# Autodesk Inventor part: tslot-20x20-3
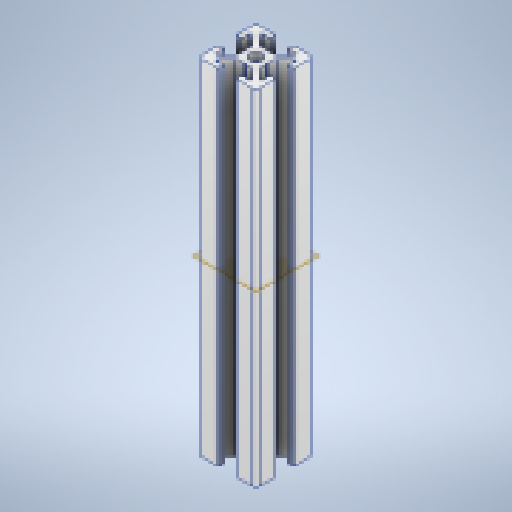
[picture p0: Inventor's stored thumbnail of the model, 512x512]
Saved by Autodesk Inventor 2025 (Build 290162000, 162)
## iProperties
Created: 2025-03
Part Number: tslot-20x20-3
Material: Alluminio 6061
Document SubType Name: Modeling
Designer: Ryzen5700u
Density: 2.7 g/cm^3
Appearance: Alluminio - Piatto
Author: Ryzen5700u
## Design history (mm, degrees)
feature "Base1"
sketch "Schizzo1"
  geometry: L1 (3.761, -16)-(4.7, -16) reference; L2 (3.761, -16)-(0.7, -12.939) reference; L3 (0.7, -12.939)-(0.7, -10.52) reference; L4 (0.4, -10)-(0.7, -10.52) reference; L5 (0.4, -10)-(0.7, -9.48) reference; L6 (0.7, -7.061)-(0.7, -9.48) reference; L7 (3.761, -4)-(0.7, -7.061) reference; L8 (3.761, -4)-(4.7, -4) reference; L9 (4.7, -4)-(4.7, -7) reference; L10 (4.7, -7)-(6.4, -7) reference; L11 (6.7, -6.7)-(6.7, -1) reference; L12 (5.7, 0)-(0, 0) reference; L13 (-0.3, -2)-(-0.3, -0.3) reference; L14 (2.7, -2)-(-0.3, -2) reference; L15 (2.7, -2.939)-(2.7, -2) reference; L16 (2.7, -2.939)-(-0.361, -6) reference; L17 (-0.361, -6)-(-2.78, -6) reference; L18 (-3.3, -6.3)-(-2.78, -6) reference; L19 (-3.3, -6.3)-(-3.82, -6) reference; L20 (-6.239, -6)-(-3.82, -6) reference; L21 (-9.3, -2.939)-(-6.239, -6) reference; L22 (-9.3, -2.939)-(-9.3, -2) reference; L23 (-9.3, -2)-(-6.3, -2) reference; L24 (-6.3, -2)-(-6.3, -0.3) reference; L25 (-12.3, 0)-(-6.6, 0) reference; L26 (-13.3, -6.7)-(-13.3, -1) reference; L27 (-11.3, -7)-(-13, -7) reference; L28 (-11.3, -4)-(-11.3, -7) reference; L29 (-10.361, -4)-(-11.3, -4) reference; L30 (-10.361, -4)-(-7.3, -7.061) reference; L31 (-7.3, -7.061)-(-7.3, -9.48) reference; L32 (-7, -10)-(-7.3, -9.48) reference; L33 (-7, -10)-(-7.3, -10.52) reference; L34 (-7.3, -12.939)-(-7.3, -10.52) reference; L35 (-10.361, -16)-(-7.3, -12.939) reference; L36 (-10.361, -16)-(-11.3, -16) reference; L37 (-11.3, -16)-(-11.3, -13) reference; L38 (-11.3, -13)-(-13, -13) reference; L39 (-13.3, -13.3)-(-13.3, -19) reference; L40 (-12.3, -20)-(-6.6, -20) reference; L41 (-6.3, -18)-(-6.3, -19.7) reference; L42 (-9.3, -18)-(-6.3, -18) reference; L43 (-9.3, -17.061)-(-9.3, -18) reference; L44 (-9.3, -17.061)-(-6.239, -14) reference; L45 (-6.239, -14)-(-3.82, -14) reference; L46 (-3.3, -13.7)-(-3.82, -14) reference; L47 (-3.3, -13.7)-(-2.78, -14) reference; L48 (-0.361, -14)-(-2.78, -14) reference; L49 (2.7, -17.061)-(-0.361, -14) reference; L50 (2.7, -17.061)-(2.7, -18) reference; L51 (2.7, -18)-(-0.3, -18) reference; L52 (-0.3, -18)-(-0.3, -19.7) reference; L53 (5.7, -20)-(0, -20) reference; L54 (6.7, -13.3)-(6.7, -19) reference; L55 (4.7, -13)-(6.4, -13) reference; L56 (4.7, -16)-(4.7, -13) reference; C1 r 2.1 at (-3.3, -10) reference; A1 r 0.3 centre (6.4, -6.7) between (6.4, -7) and (6.7, -6.7) reference; A2 r 1 centre (5.7, -1) between (6.7, -1) and (5.7, 0) reference; A3 r 0.3 centre (0, -0.3) between (0, 0) and (-0.3, -0.3) reference; A4 r 0.3 centre (-6.6, -0.3) between (-6.3, -0.3) and (-6.6, 0) reference; A5 r 1 centre (-12.3, -1) between (-12.3, 0) and (-13.3, -1) reference; A6 r 0.3 centre (-13, -6.7) between (-13.3, -6.7) and (-13, -7) reference; A7 r 0.3 centre (-13, -13.3) between (-13, -13) and (-13.3, -13.3) reference; A8 r 1 centre (-12.3, -19) between (-13.3, -19) and (-12.3, -20) reference; A9 r 0.3 centre (-6.6, -19.7) between (-6.6, -20) and (-6.3, -19.7) reference; A10 r 0.3 centre (0, -19.7) between (-0.3, -19.7) and (0, -20) reference; A11 r 1 centre (5.7, -19) between (5.7, -20) and (6.7, -19) reference; A12 r 0.3 centre (6.4, -13.3) between (6.7, -13.3) and (6.4, -13) reference; 1 further point
extrude "Estrusione1" join sketch "Schizzo1" distance "d0" = 110; taper "d1" = 0 deg
node "Piano di lavoro1"
node "Solido1"
node "Linea chiusa proiettata1"
